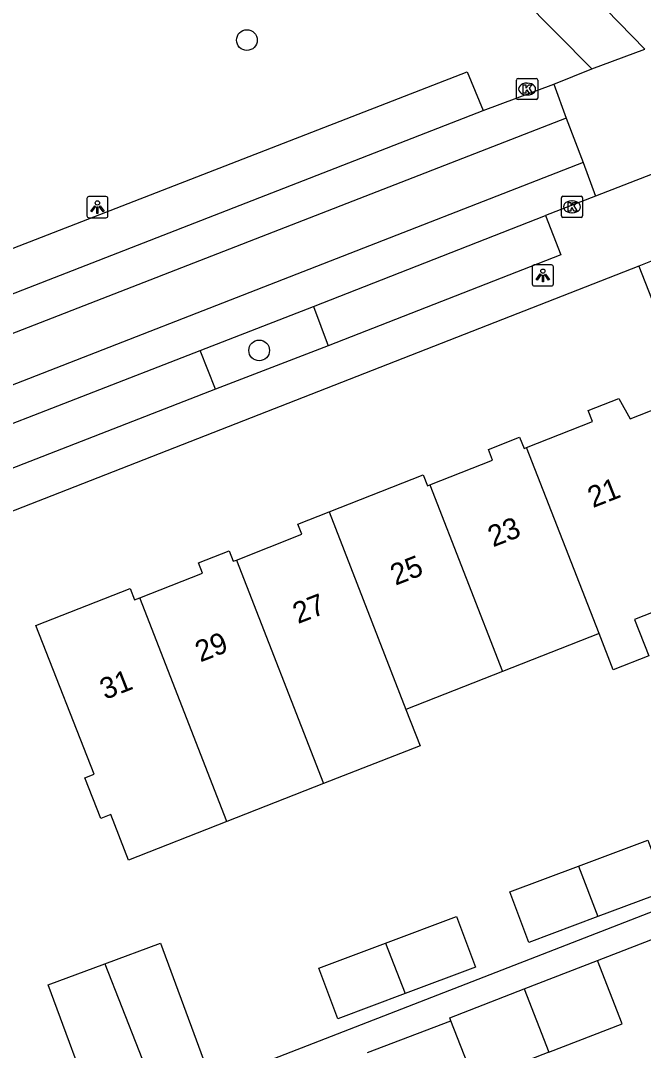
# Model space of a CAD drawing. Extents: x 159689 to 160786, y 387323 to 388339.
# Drawn here: x 160016.12 to 160045.51, y 387907.82 to 387956.43 of the extents above; entities that cross this region are included whole.
import ezdxf

# ---------------------------------------------------------------- set-up
doc = ezdxf.new("R2010")
doc.units = 0
for name, color, linetype in [('IMGEO_Boom', 7, 'Continuous'), ('IMGEO_Kolk', 7, 'Continuous'), ('IMGEO_Lichtpunt', 7, 'Continuous'), ('IMGEO_Pand', 7, 'Continuous'), ('IMGEO_Pand_nummerreeks', 7, 'Continuous'), ('IMGEO_Parkeervlak_open', 7, 'Continuous'), ('IMGEO_Rijbaan_lokaal_gesloten', 7, 'Continuous'), ('IMGEO_Rijbaan_lokaal_open', 7, 'Continuous'), ('IMGEO_Voetpad_halfverhard', 7, 'Continuous'), ('IMGEO_Voetpad_open', 7, 'Continuous')]:
    doc.layers.add(name, color=color, linetype=linetype)

msp = doc.modelspace()

# ---------------------------------------------------------------- linework, layer by layer
at = {"layer": 'IMGEO_Boom'}
for centre in [(160026.798, 387955.513), (160027.377, 387940.865)]:
    msp.add_circle(centre, 0.489, dxfattribs=at)
at = {"layer": 'IMGEO_Kolk'}
for p, q in [((160039.521, 387952.777), (160039.521, 387953.629)), ((160039.596, 387953.703), (160040.448, 387953.703)), ((160040.522, 387953.629), (160040.522, 387952.777)), ((160040.009, 387953.483), (160040.034, 387953.483)), ((160040.448, 387952.703), (160039.596, 387952.703)), ((160040.032, 387952.923), (160040.007, 387952.923)), ((160041.639, 387947.217), (160041.639, 387948.069)), ((160041.714, 387948.143), (160042.566, 387948.143)), ((160042.127, 387947.923), (160042.152, 387947.923)), ((160042.64, 387948.069), (160042.64, 387947.217)), ((160042.15, 387947.363), (160042.125, 387947.363)), ((160042.566, 387947.143), (160041.714, 387947.143))]:
    msp.add_line(p, q, dxfattribs=at)
for points in [[(160039.521, 387952.777), (160039.521, 387953.629)], [(160039.596, 387953.703), (160040.448, 387953.703)], [(160040.522, 387953.629), (160040.522, 387952.777)], [(160039.842, 387953.403), (160039.965, 387953.403), (160039.965, 387953.252), (160040.095, 387953.403), (160040.259, 387953.403), (160040.113, 387953.252), (160040.266, 387953.003), (160040.114, 387953.003), (160040.029, 387953.167), (160039.965, 387953.1), (160039.965, 387953.003), (160039.842, 387953.003), (160039.842, 387953.403)], [(160040.448, 387952.703), (160039.596, 387952.703)], [(160041.639, 387947.217), (160041.639, 387948.069)], [(160041.714, 387948.143), (160042.566, 387948.143)], [(160041.96, 387947.843), (160042.083, 387947.843), (160042.083, 387947.692), (160042.213, 387947.843), (160042.377, 387947.843), (160042.231, 387947.692), (160042.384, 387947.443), (160042.232, 387947.443), (160042.147, 387947.607), (160042.083, 387947.54), (160042.083, 387947.443), (160041.96, 387947.443), (160041.96, 387947.843)], [(160042.64, 387948.069), (160042.64, 387947.217)], [(160042.566, 387947.143), (160041.714, 387947.143)]]:
    msp.add_lwpolyline(points, dxfattribs=at)
for centre, start, end in [((160039.598, 387953.627), 91.552, 178.448), ((160039.598, 387953.627), 91.552, 178.448), ((160040.446, 387953.627), 1.552, 88.448), ((160040.446, 387953.627), 1.552, 88.448), ((160039.598, 387952.779), 181.552, 268.448), ((160039.598, 387952.779), 181.552, 268.448), ((160040.446, 387952.779), 271.552, 358.448), ((160040.446, 387952.779), 271.552, 358.448), ((160041.716, 387948.067), 91.552, 178.448), ((160041.716, 387948.067), 91.552, 178.448), ((160042.564, 387948.067), 1.552, 88.448), ((160042.564, 387948.067), 1.552, 88.448), ((160041.716, 387947.219), 181.552, 268.448), ((160041.716, 387947.219), 181.552, 268.448), ((160042.564, 387947.219), 271.552, 358.448), ((160042.564, 387947.219), 271.552, 358.448)]:
    msp.add_arc(centre, 0.0765, start, end, dxfattribs=at)
for centre, major_axis, ratio, start_param, end_param in [((160040.008, 387953.203), (-0.387, 0.002), 0.722429, 4.712389, 7.853982), ((160040.033, 387953.203), (-0.39, 0.002), 0.717154, 1.570796, 4.712389), ((160042.126, 387947.643), (-0.387, 0.002), 0.722429, 4.712389, 7.853982), ((160042.151, 387947.643), (-0.39, 0.002), 0.717154, 1.570796, 4.712389)]:
    msp.add_ellipse(centre, major_axis=major_axis, ratio=ratio, start_param=start_param, end_param=end_param, dxfattribs=at)
at = {"layer": 'IMGEO_Lichtpunt'}
for p, q in [((160019.245, 387948.03), (160019.245, 387947.223)), ((160019.245, 387948.03), (160019.245, 387947.223)), ((160020.147, 387948.125), (160019.339, 387948.125)), ((160020.147, 387948.125), (160019.339, 387948.125)), ((160020.241, 387947.223), (160020.241, 387948.03)), ((160020.241, 387947.223), (160020.241, 387948.03)), ((160019.339, 387947.129), (160020.147, 387947.129)), ((160019.339, 387947.129), (160020.147, 387947.129)), ((160041.168, 387944.904), (160040.36, 387944.904)), ((160041.168, 387944.904), (160040.36, 387944.904)), ((160040.266, 387944.809), (160040.266, 387944.002)), ((160040.266, 387944.809), (160040.266, 387944.002)), ((160041.262, 387944.002), (160041.262, 387944.809)), ((160041.262, 387944.002), (160041.262, 387944.809)), ((160040.36, 387943.908), (160041.168, 387943.908)), ((160040.36, 387943.908), (160041.168, 387943.908))]:
    msp.add_line(p, q, dxfattribs=at)
for points in [[(160019.619, 387947.694), (160019.658, 387947.666), (160019.47, 387947.404), (160019.432, 387947.431), (160019.619, 387947.694)], [(160019.721, 387947.646), (160019.768, 387947.646), (160019.768, 387947.324), (160019.721, 387947.324), (160019.721, 387947.646)], [(160019.831, 387947.666), (160019.869, 387947.693), (160020.056, 387947.431), (160020.017, 387947.403), (160019.831, 387947.666)], [(160040.64, 387944.473), (160040.679, 387944.445), (160040.491, 387944.183), (160040.453, 387944.21), (160040.64, 387944.473)], [(160040.742, 387944.425), (160040.789, 387944.425), (160040.789, 387944.103), (160040.742, 387944.103), (160040.742, 387944.425)], [(160040.852, 387944.445), (160040.89, 387944.472), (160041.077, 387944.21), (160041.038, 387944.182), (160040.852, 387944.445)]]:
    msp.add_lwpolyline(points, dxfattribs=at)
for centre in [(160019.744, 387947.828), (160040.765, 387944.607)]:
    msp.add_circle(centre, 0.0994, dxfattribs=at)
for centre, start, end in [((160019.339, 387948.03), 90, 180), ((160019.339, 387948.03), 90, 180), ((160020.147, 387948.03), 0, 90), ((160020.147, 387948.03), 0, 90), ((160019.339, 387947.223), 180, 270), ((160019.339, 387947.223), 180, 270), ((160020.147, 387947.223), 270, 0), ((160020.147, 387947.223), 270, 360), ((160040.36, 387944.809), 90, 180), ((160040.36, 387944.809), 90, 180), ((160041.168, 387944.809), 0, 90), ((160041.168, 387944.809), 0, 90), ((160040.36, 387944.002), 180, 270), ((160040.36, 387944.002), 180, 270), ((160041.168, 387944.002), 270, 0), ((160041.168, 387944.002), 270, 360)]:
    msp.add_arc(centre, 0.0946, start, end, dxfattribs=at)
at = {"layer": 'IMGEO_Pand'}
for points in [[(160039.997, 387936.288), (160043.101, 387937.508), (160042.898, 387938.024), (160044.342, 387938.592), (160044.89, 387937.638), (160047.681, 387938.736)], [(160035.429, 387934.522), (160038.395, 387935.688), (160038.195, 387936.195), (160039.666, 387936.773), (160039.876, 387936.24), (160039.997, 387936.288)], [(160043.42, 387927.502), (160039.997, 387936.288)], [(160030.672, 387933.24), (160035.115, 387934.987), (160035.316, 387934.478), (160035.429, 387934.522)], [(160035.429, 387934.522), (160038.86, 387925.71)], [(160026.299, 387930.971), (160029.386, 387932.185), (160029.199, 387932.661), (160030.672, 387933.24)], [(160030.672, 387933.24), (160034.303, 387923.918)], [(160021.74, 387929.18), (160024.703, 387930.344), (160024.511, 387930.832), (160025.962, 387931.403), (160026.154, 387930.914), (160026.299, 387930.971)], [(160026.299, 387930.971), (160030.412, 387920.414)], [(160050.938, 387930.458), (160045.095, 387928.16), (160045.766, 387926.452), (160044.087, 387925.791), (160043.42, 387927.502)], [(160025.853, 387918.622), (160021.216, 387916.798), (160020.369, 387918.952), (160019.905, 387918.769), (160019.148, 387920.695), (160019.586, 387920.868), (160016.832, 387927.873), (160021.284, 387929.623), (160021.496, 387929.084), (160021.74, 387929.18)], [(160025.853, 387918.622), (160021.74, 387929.18)], [(160043.42, 387927.502), (160038.86, 387925.71)], [(160038.86, 387925.71), (160034.303, 387923.918)], [(160034.303, 387923.918), (160034.969, 387922.206), (160030.412, 387920.414)], [(160030.412, 387920.414), (160025.853, 387918.622)], [(160042.44, 387916.516), (160045.717, 387917.745), (160046.613, 387915.357), (160043.365, 387914.139)], [(160043.365, 387914.139), (160040.108, 387912.917), (160039.213, 387915.306), (160042.44, 387916.516)], [(160042.44, 387916.516), (160043.365, 387914.139)], [(160033.343, 387912.89), (160036.693, 387914.146), (160037.588, 387911.757), (160034.27, 387910.513)], [(160020.092, 387911.904), (160022.715, 387912.877), (160025.003, 387906.707), (160022.492, 387905.776)], [(160034.27, 387910.513), (160031.084, 387909.318), (160030.188, 387911.707), (160033.343, 387912.89)], [(160033.343, 387912.89), (160034.27, 387910.513)], [(160022.492, 387905.776), (160019.702, 387904.741), (160017.414, 387910.912), (160020.092, 387911.904)], [(160020.092, 387911.904), (160022.492, 387905.776)], [(160039.887, 387910.722), (160043.341, 387912.063)], [(160041.054, 387907.731), (160044.503, 387909.07), (160043.341, 387912.063)], [(160036.424, 387909.216), (160036.37, 387909.356), (160039.887, 387910.722)], [(160039.887, 387910.722), (160041.054, 387907.731)], [(160041.054, 387907.731), (160037.532, 387906.363), (160036.424, 387909.216)]]:
    msp.add_lwpolyline(points, dxfattribs=at)
at = {"layer": 'IMGEO_Parkeervlak_open'}
for points in [[(159976.881, 387928.393), (159976.14, 387930.3), (160037.196, 387954.02), (160037.945, 387952.192)], [(160029.943, 387942.932), (160030.636, 387941.086)], [(160025.316, 387939.042), (160024.591, 387940.857)]]:
    msp.add_lwpolyline(points, dxfattribs=at)
at = {"layer": 'IMGEO_Rijbaan_lokaal_gesloten'}
for points in [[(160037.945, 387952.192), (160041.286, 387953.436)], [(159976.881, 387928.393), (160037.945, 387952.192)], [(160041.859, 387951.835), (159977.527, 387926.791), (159949.223, 387915.763)], [(160042.67, 387949.729), (159950.038, 387913.604)], [(160043.249, 387948.15), (160040.896, 387947.234)], [(160029.943, 387942.932), (160040.896, 387947.234)], [(160024.591, 387940.857), (160029.943, 387942.932)], [(160013.407, 387936.521), (160024.591, 387940.857)]]:
    msp.add_lwpolyline(points, dxfattribs=at)
at = {"layer": 'IMGEO_Rijbaan_lokaal_open'}
for points in [[(160043.077, 387954.15), (160045.579, 387955.091)], [(160041.286, 387953.436), (160043.077, 387954.15)], [(160041.286, 387953.436), (160041.859, 387951.835)], [(160041.859, 387951.835), (160042.67, 387949.729)], [(160048.884, 387950.337), (160043.249, 387948.15)], [(160042.67, 387949.729), (160043.249, 387948.15)]]:
    msp.add_lwpolyline(points, dxfattribs=at)
at = {"layer": 'IMGEO_Voetpad_halfverhard'}
for points in [[(160045.579, 387955.091), (160039.464, 387961.379), (160027.804, 387973.736)], [(160025.236, 387972.702), (160036.357, 387960.96), (160043.077, 387954.15)]]:
    msp.add_lwpolyline(points, dxfattribs=at)
at = {"layer": 'IMGEO_Voetpad_open'}
for points in [[(160040.896, 387947.234), (160041.612, 387945.372), (160030.636, 387941.086)], [(160046.468, 387945.307), (160045.29, 387944.846)], [(160045.29, 387944.846), (160000, 387927.125), (159981.828, 387920.015)], [(160045.29, 387944.846), (160047.681, 387938.736)], [(160030.636, 387941.086), (160025.316, 387939.042)], [(160025.316, 387939.042), (160014.109, 387934.677), (160013.407, 387936.521)], [(160050.938, 387930.458), (160055.714, 387918.166), (159992.266, 387893.513), (159992.118, 387893.867)], [(160043.341, 387912.063), (160045.861, 387913.041), (160047.801, 387913.794)], [(160032.492, 387907.728), (160036.424, 387909.216)]]:
    msp.add_lwpolyline(points, dxfattribs=at)

# ---------------------------------------------------------------- texts
at = {"layer": 'IMGEO_Pand_nummerreeks'}
for s, p in [('21', (160043.125, 387933.419)), ('23', (160038.416, 387931.566)), ('25', (160033.811, 387929.755)), ('27', (160029.207, 387927.944)), ('29', (160024.603, 387926.133)), ('31', (160020.104, 387924.362))]:
    msp.add_text(s, height=1, rotation=21.475, dxfattribs=at).set_placement(p)

doc.saveas('drawing.dxf')
